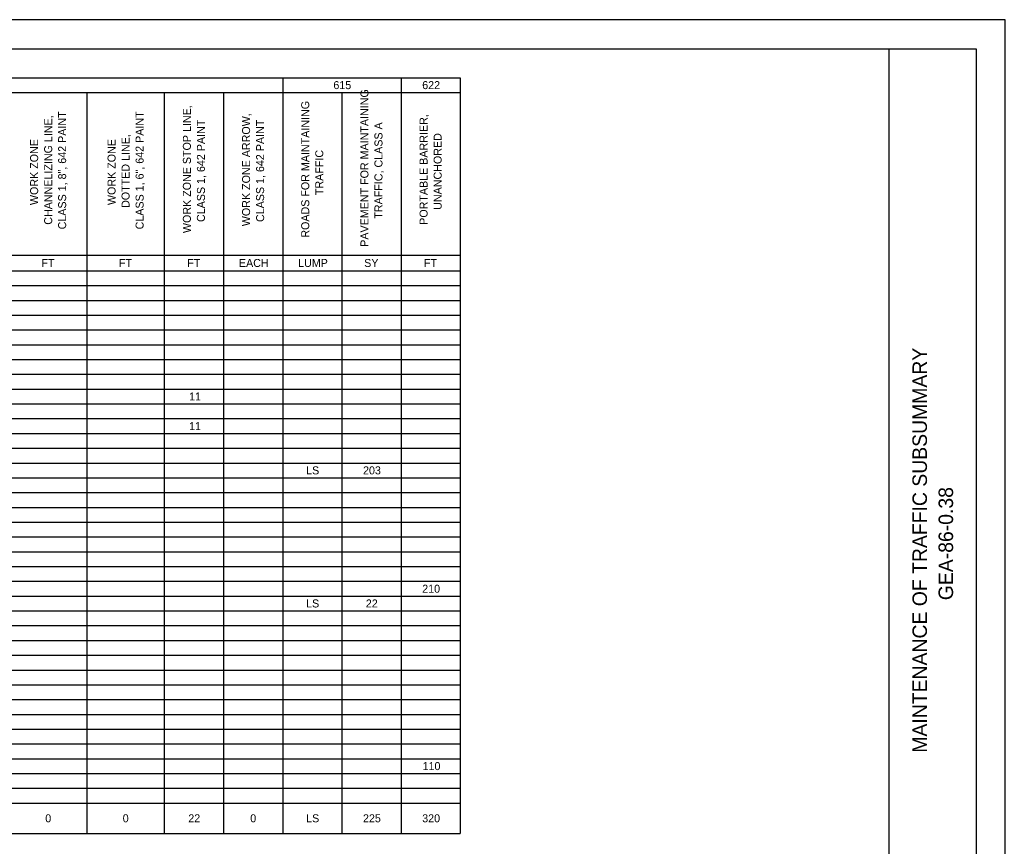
# Model space of a CAD drawing. Extents: x 0 to 34, y 0 to 22.
# Drawn here: x 17.01 to 34, y 7.75 to 22 of the extents above; entities that cross this region are included whole.
import ezdxf

# ---------------------------------------------------------------- set-up
doc = ezdxf.new("R2010")
doc.units = 0
for name, color, linetype in [('SH_Border', 7, 'Continuous'), ('SH_Cut_Line', 7, 'Continuous'), ('SH_Data', 7, 'Continuous'), ('SH_Text', 7, 'Continuous')]:
    doc.layers.add(name, color=color, linetype=linetype)

msp = doc.modelspace()

# ---------------------------------------------------------------- linework, layer by layer
at = {"layer": 'SH_Border'}
msp.add_line((32, 0.5), (32, 21.5), dxfattribs=at)
msp.add_lwpolyline([(1.5, 21.5), (33.5, 21.5), (33.5, 0.5), (1.5, 0.5)], close=True, dxfattribs=at)
at = {"layer": 'SH_Cut_Line'}
msp.add_lwpolyline([(0, 0), (34, 0), (34, 22), (0, 22)], close=True, dxfattribs=at)
at = {"layer": 'SH_Text'}
for p, q in [((2, 21), (24.605, 21)), ((21.545, 21), (21.545, 7.965)), ((23.585, 21), (23.585, 7.965)), ((24.605, 21), (24.605, 7.965)), ((8.045, 20.745), (24.605, 20.745)), ((18.17, 20.745), (18.17, 7.965)), ((19.505, 20.745), (19.505, 7.965)), ((20.525, 20.745), (20.525, 7.965)), ((22.565, 20.745), (22.565, 7.965)), ((8.045, 17.94), (24.605, 17.94)), ((2, 17.67), (24.605, 17.67)), ((2, 17.415), (24.605, 17.415)), ((2, 17.16), (24.605, 17.16)), ((2, 16.905), (24.605, 16.905)), ((2, 16.65), (24.605, 16.65)), ((2, 16.395), (24.605, 16.395)), ((2, 16.14), (24.605, 16.14)), ((2, 15.885), (24.605, 15.885)), ((2, 15.63), (24.605, 15.63)), ((2, 15.375), (24.605, 15.375)), ((2, 15.12), (24.605, 15.12)), ((2, 14.865), (24.605, 14.865)), ((2, 14.61), (24.605, 14.61)), ((2, 14.355), (24.605, 14.355)), ((2, 14.1), (24.605, 14.1)), ((2, 13.845), (24.605, 13.845)), ((2, 13.59), (24.605, 13.59)), ((2, 13.335), (24.605, 13.335)), ((2, 13.08), (24.605, 13.08)), ((2, 12.825), (24.605, 12.825)), ((2, 12.57), (24.605, 12.57)), ((2, 12.315), (24.605, 12.315)), ((2, 12.06), (24.605, 12.06)), ((2, 11.805), (24.605, 11.805)), ((2, 11.55), (24.605, 11.55)), ((2, 11.295), (24.605, 11.295)), ((2, 11.04), (24.605, 11.04)), ((2, 10.785), (24.605, 10.785)), ((2, 10.53), (24.605, 10.53)), ((2, 10.275), (24.605, 10.275)), ((2, 10.02), (24.605, 10.02)), ((2, 9.765), (24.605, 9.765)), ((2, 9.51), (24.605, 9.51)), ((2, 9.255), (24.605, 9.255)), ((2, 9), (24.605, 9)), ((2, 8.745), (24.605, 8.745)), ((2, 8.49), (24.605, 8.49)), ((2, 7.965), (24.605, 7.965))]:
    msp.add_line(p, q, dxfattribs=at)

# ---------------------------------------------------------------- texts
at = {"layer": 'SH_Data'}
for s, p in [('MAINTENANCE OF TRAFFIC SUBSUMMARY', (32.65, 9.359)), ('GEA-86-0.38', (33.1, 11.989))]:
    msp.add_text(s, height=0.25, rotation=90, dxfattribs=at).set_placement(p)
at = {"layer": 'SH_Text'}
for s, p in [('615', (22.419, 20.803)), ('622', (23.95, 20.803)), ('FT', (17.388, 17.736)), ('FT', (18.723, 17.736)), ('FT', (19.9, 17.736)), ('EACH', (20.791, 17.736)), ('LUMP', (21.811, 17.736)), ('SY', (22.95, 17.736)), ('FT', (23.98, 17.736)), ('11', (19.932, 15.433)), ('11', (19.932, 14.923)), ('LS', (21.949, 14.159)), ('203', (22.93, 14.159)), ('210', (23.95, 12.118)), ('LS', (21.949, 11.864)), ('22', (22.978, 11.864)), ('110', (23.956, 9.059)), ('0', (17.453, 8.159)), ('0', (18.788, 8.159)), ('22', (19.918, 8.159)), ('0', (20.986, 8.159)), ('LS', (21.949, 8.159)), ('225', (22.929, 8.159)), ('320', (23.95, 8.159))]:
    msp.add_text(s, height=0.138, dxfattribs=at).set_placement(p)
for s, p in [('PAVEMENT FOR MAINTAINING ', (23.023, 18.084)), ('ROADS FOR MAINTAINING ', (22.003, 18.241)), ('CLASS 1, 8", 642 PAINT', (17.813, 18.384)), ('CLASS 1, 6", 642 PAINT', (19.148, 18.384)), ('WORK ZONE STOP LINE, ', (19.963, 18.32)), ('CHANNELIZING LINE,', (17.572, 18.464)), ('CLASS 1, 642 PAINT', (20.205, 18.511)), ('WORK ZONE ARROW, ', (20.983, 18.439)), ('CLASS 1, 642 PAINT', (21.225, 18.511)), ('TRAFFIC, CLASS A', (23.265, 18.569)), ('PORTABLE BARRIER, ', (24.043, 18.463)), ('WORK ZONE', (17.33, 18.803)), ('WORK ZONE', (18.665, 18.803)), ('DOTTED LINE,', (18.906, 18.754)), ('UNANCHORED', (24.285, 18.721)), ('TRAFFIC', (22.245, 18.975))]:
    msp.add_text(s, height=0.138, rotation=90, dxfattribs=at).set_placement(p)

doc.saveas('drawing.dxf')
